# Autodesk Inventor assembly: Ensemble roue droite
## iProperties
Author: Flavien MARTY
Shininess: 21.0
PropertySet Name: _Private Model Information
Created: 2001-10
Part Number: Ensemble roue droite
Document SubType Name: Assemblage
Designer: Flavien MARTY
Control State: 0
Master: False
Checked Out: False
PropertySet Name: Design Tracking Control
Density: 0.0
Volumn: 0.0
Area: 0.0
PropertySet Name: Model Information
